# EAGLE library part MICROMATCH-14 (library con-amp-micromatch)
MicroMaTch 14 8-215464-4 / 1-215464-4 Drawing Number C-215464 DDEController.pdf
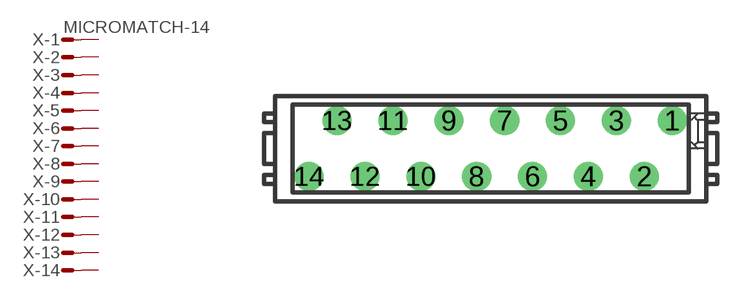
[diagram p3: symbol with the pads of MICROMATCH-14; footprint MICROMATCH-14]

Designator prefix X; gates -1=MV -2=M -3=M -4=M -5=M -6=M -7=M -8=M -9=M -10=M -11=M -12=M -13=M -14=M

## MICROMATCH-14 (MF: FARNELL; MPN: 8-215464-4; OC_FARNELL: 3784678; OC_NEWARK: 19J6431)  [MICROMATCH-14]
1  -1:S  pas
2  -2:S  pas
3  -3:S  pas
4  -4:S  pas
5  -5:S  pas
6  -6:S  pas
7  -7:S  pas
8  -8:S  pas
9  -9:S  pas
10  -10:S  pas
11  -11:S  pas
12  -12:S  pas
13  -13:S  pas
14  -14:S  pas

## Footprint MICROMATCH-14 (pad centres in mm)
MicroMaTch 14 8-215464-4 / 1-215464-4 Drawing Number C-215464 DDEController.pdf
drill 0.813 round: 1 8.255,1.27; 2 6.985,-1.27; 3 5.715,1.27; 4 4.445,-1.27; 5 3.175,1.27; 6 1.905,-1.27; 7 0.635,1.27; 8 -0.635,-1.27; 9 -1.905,1.27; 10 -3.175,-1.27; 11 -4.445,1.27; 12 -5.715,-1.27; 13 -6.985,1.27; 14 -8.255,-1.27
